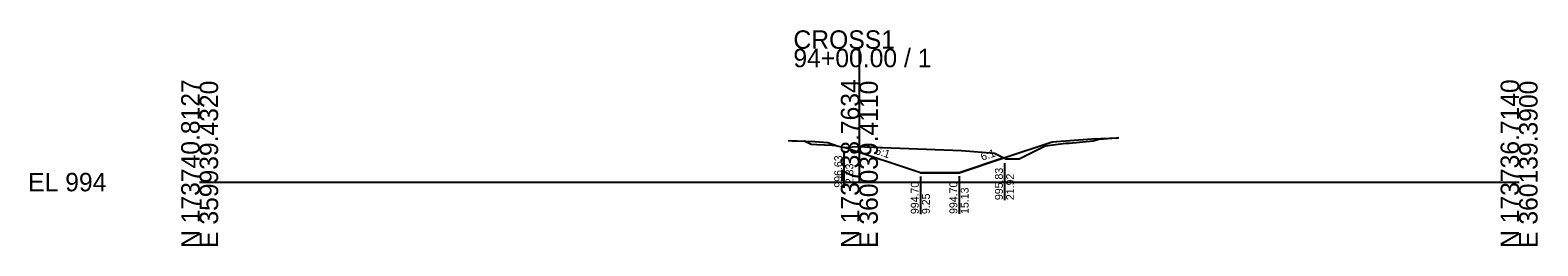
# Model space of a CAD drawing. Extents: x -26 to 1403, y -10 to 11027.
# Drawn here: x -25.7 to 202.8, y 8990.3 to 9023.1 of the extents above; entities that cross this region are included whole.
import ezdxf

# ---------------------------------------------------------------- set-up
doc = ezdxf.new("R2010")
doc.units = 0
for name, color, linetype in [('Default', 7, 'Continuous'), ('P_E_XS_Ground', 7, 'Continuous'), ('P_XS', 7, 'Continuous'), ('P_XS_EAR_CommonGrnd', 7, 'Continuous'), ('P_XS_Lane', 7, 'Continuous'), ('P_XS_Rock', 7, 'Continuous')]:
    doc.layers.add(name, color=color, linetype=linetype)

msp = doc.modelspace()

# ---------------------------------------------------------------- linework, layer by layer
at = {"layer": 'Default'}
for p, q in [((100, 9000), (100, 9020.24)), ((0, 9000), (100, 9000)), ((100, 9000), (200, 9000))]:
    msp.add_line(p, q, dxfattribs=at)
at = {"layer": 'P_E_XS_Ground'}
for p, q in [((135.44, 9006.27), (136.3, 9006.5)), ((136.3, 9006.5), (138.92, 9006.72)), ((138.92, 9006.72), (139.33, 9006.75)), ((89.48, 9006.31), (90.02, 9006.23)), ((90.02, 9006.23), (91.65, 9006.24)), ((91.65, 9006.24), (92.7, 9005.78)), ((92.7, 9005.78), (93.56, 9005.73)), ((93.56, 9005.73), (95.89, 9005.62)), ((95.89, 9005.62), (96.4, 9005.56)), ((96.4, 9005.56), (97.67, 9005.26)), ((97.67, 9005.26), (99.5, 9005.41)), ((99.5, 9005.41), (115.5, 9004.77)), ((115.5, 9004.77), (120.5, 9004.37)), ((120.5, 9004.37), (122.2, 9003.52)), ((124.2, 9003.52), (128.17, 9005.5)), ((128.17, 9005.5), (131.3, 9005.92)), ((131.3, 9005.92), (131.82, 9005.93)), ((131.82, 9005.93), (135.44, 9006.27)), ((122.2, 9003.52), (124.2, 9003.52))]:
    msp.add_line(p, q, dxfattribs=at)
at = {"layer": 'P_XS'}
for p, q in [((129.23, 9006.1), (135.23, 9006.58)), ((135.23, 9006.58), (139.23, 9006.74)), ((89.23, 9006.31), (93.23, 9006.15)), ((93.23, 9006.15), (95.23, 9005.99)), ((95.23, 9005.99), (96.8, 9005.46)), ((121.92, 9003.66), (129.23, 9006.1))]:
    msp.add_line(p, q, dxfattribs=at)
at = {"layer": 'P_XS_EAR_CommonGrnd'}
msp.add_lwpolyline([(120.5, 9004.37), (121.92, 9003.66), (115.13, 9001.4), (109.25, 9001.4), (97.67, 9005.26), (99.5, 9005.41), (115.5, 9004.77)], close=True, dxfattribs=at)
at = {"layer": 'P_XS_Lane'}
for p, q in [((109.25, 9001.4), (97.67, 9005.26)), ((115.13, 9001.4), (121.92, 9003.66)), ((109.25, 9001.4), (115.13, 9001.4))]:
    msp.add_line(p, q, dxfattribs=at)
at = {"layer": 'P_XS_Rock'}
for p, q in [((97.64, 9004.76), (97.64, 8999.15)), ((122, 9002.88), (122, 8997.26)), ((109.24, 9000.85), (109.24, 8995.14)), ((115.1, 9000.88), (115.1, 8995.16))]:
    msp.add_line(p, q, dxfattribs=at)

# ---------------------------------------------------------------- texts
at = {"layer": 'Default'}
for s, p in [('CROSS1', (90, 9020.24)), ('94+00.00 / 1', (90, 9017.44)), ('EL 994', (-26, 8998.6))]:
    msp.add_text(s, height=2.8, dxfattribs=at).set_placement(p)
for s, p in [('N 173740.8127', (0, 8990)), ('E 359939.4320', (2.8, 8990)), ('N 173738.7634', (100, 8990)), ('E 360039.4110', (102.8, 8990)), ('N 173736.7140', (200, 8990)), ('E 360139.3900', (202.8, 8990))]:
    msp.add_text(s, height=2.8, rotation=90, dxfattribs=at).set_placement(p)
at = {"layer": 'P_XS_Rock'}
for s, rotation, p in [('6:1', 341.5651, (102.3, 9004.29)), ('6:1', 18.4349, (118.62, 9003.22)), ('996.63', 90, (97.39, 8999.15)), ('-2.33', 90, (99.09, 8999.15)), ('995.83', 90, (121.75, 8997.26)), ('994.70', 90, (108.99, 8995.14)), ('994.70', 90, (114.85, 8995.16)), ('21.92', 90, (123.45, 8997.26)), ('9.25', 90, (110.69, 8995.14)), ('15.13', 90, (116.55, 8995.16))]:
    msp.add_text(s, height=1.2, rotation=rotation, dxfattribs=at).set_placement(p)

doc.saveas('drawing.dxf')
